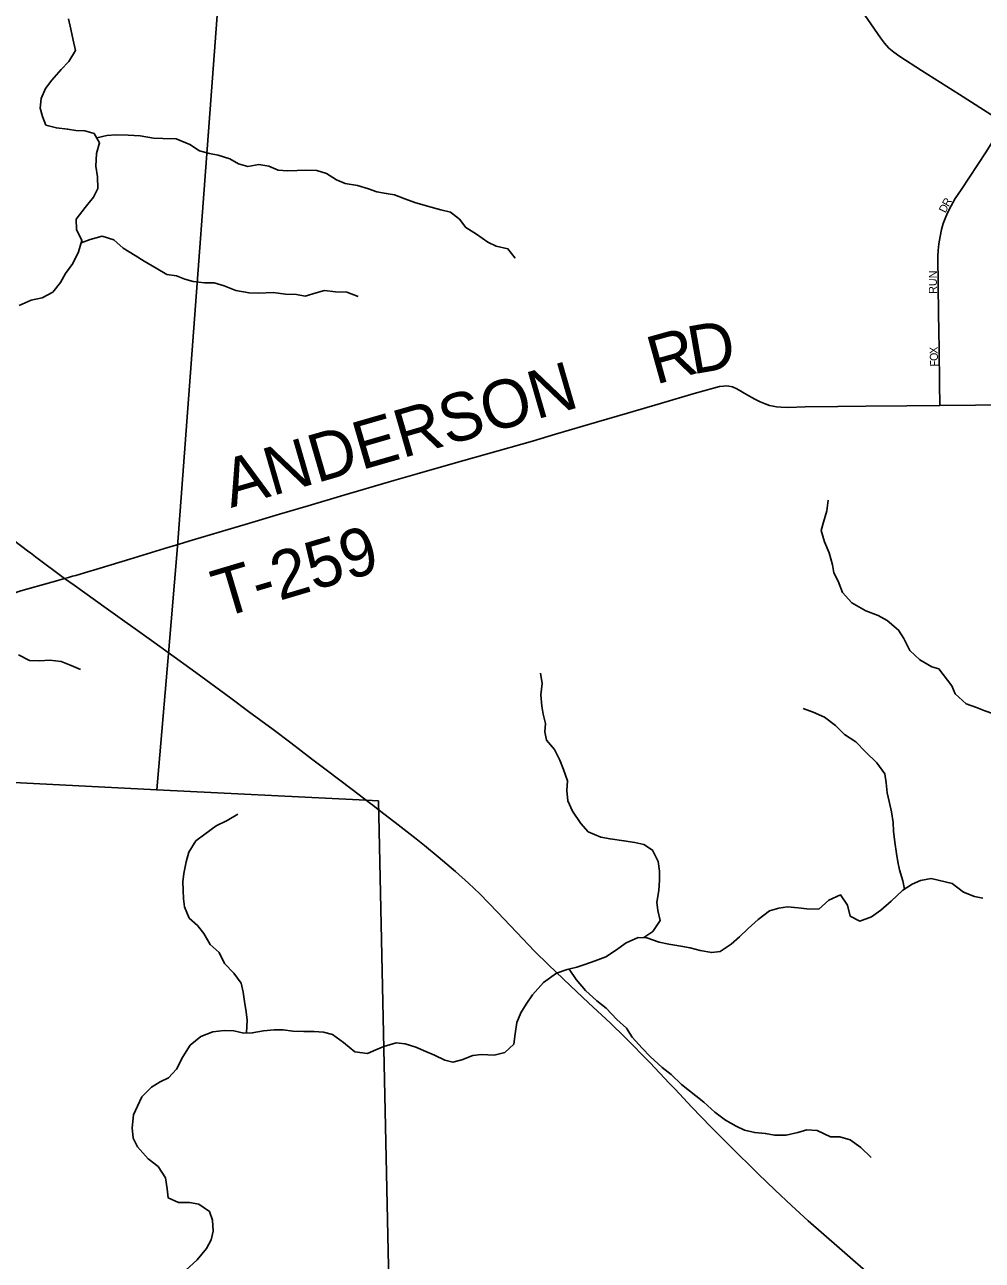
# Model space of a CAD drawing. Extents: x 1442749 to 1756758, y 235267 to 677782.
# Drawn here: x 1574676 to 1580655, y 536473 to 544190 of the extents above; entities that cross this region are included whole.
import ezdxf

# ---------------------------------------------------------------- set-up
doc = ezdxf.new("R2010")
doc.units = 0
for name, color, linetype in [('GM_X_County_Road', 7, 'Continuous'), ('GM_X_Major_River', 7, 'Continuous'), ('GM_X_Minor_River', 7, 'Continuous'), ('GM_X_State_Route', 7, 'Continuous'), ('GM_X_Township', 7, 'Continuous'), ('GM_X_Township_Road', 7, 'Continuous'), ('GM_X_Township_Road_Text', 7, 'Continuous'), ('GM_X_Township_Subdivision', 7, 'Continuous'), ('GM_X_Township_Subdivision_Text', 7, 'Continuous')]:
    doc.layers.add(name, color=color, linetype=linetype)

msp = doc.modelspace()

# ---------------------------------------------------------------- linework, layer by layer
at = {"layer": 'GM_X_County_Road'}
for points in [[(1579800.4, 544427.6), (1580018.8, 544108.2), (1580045, 544075), (1580072.2, 544044.6), (1580103.2, 544018.7), (1580139.8, 543991.7), (1580275, 543905.1), (1580513, 543753.6), (1580736.8, 543610.2)], [(1574565.9, 539401), (1574562.6, 539789.4), (1574561.3, 539916.8), (1574559.2, 540070.2), (1574557.6, 540184.8), (1574556.2, 540293), (1574553.5, 540476.5), (1574555.5, 540552.4), (1574557.3, 540565.8), (1574559.3, 540575.6), (1574561.7, 540586.3), (1574569, 540601.4), (1574576.8, 540612.2), (1574587.6, 540622.4), (1574597.8, 540630.3), (1574608.1, 540637.1), (1574617.4, 540642), (1574627.6, 540646.9), (1574651.5, 540654.2), (1574845.2, 540708.9), (1574867.7, 540715.4), (1574924.4, 540732.1)]]:
    msp.add_lwpolyline(points, dxfattribs=at)
at = {"layer": 'GM_X_Major_River'}
for points in [[(1576044.8, 537892.5), (1576096.8, 537893.1), (1576167.2, 537907.2), (1576233.4, 537913.4), (1576289.3, 537911.8), (1576349.1, 537904.1), (1576419.1, 537902.2), (1576483.1, 537902.4), (1576541, 537898.8), (1576598.5, 537883.2), (1576667.1, 537833.2), (1576737.4, 537775.2), (1576815.2, 537765.1), (1576867.8, 537787.6), (1576918.4, 537808.3), (1576995.1, 537832.2), (1577050.9, 537824.6), (1577118.3, 537804.7), (1577179.5, 537777), (1577234.8, 537753.4), (1577298, 537723.6), (1577349.6, 537710.2), (1577406, 537724.7), (1577474.8, 537752.8), (1577527, 537757.4), (1577606.9, 537753.2), (1577673.4, 537771.3), (1577728.9, 537823.9), (1577738.7, 537887.7), (1577748.7, 537957.5), (1577774.5, 538018.9), (1577806, 538072.1), (1577845.7, 538131.1), (1577915.9, 538207.3), (1577995.6, 538267.2), (1578062.2, 538289.3), (1578122.6, 538303.7), (1578173.1, 538320.3), (1578237.8, 538342.6), (1578304.5, 538368.8), (1578363.6, 538407.2), (1578431, 538455.4), (1578506, 538489.3), (1578559.9, 538487.9), (1578637.1, 538459.7), (1578696.8, 538448), (1578772.5, 538435.9), (1578830.1, 538424.3), (1578893.7, 538408.5), (1578965.3, 538394.5), (1579017.5, 538401.1), (1579086.8, 538447.2), (1579138.1, 538493.9), (1579193.6, 538544.4), (1579255.2, 538600.8), (1579326.8, 538654.9), (1579385.3, 538673.3), (1579437.5, 538679.9), (1579505.3, 538674), (1579559.2, 538668.5), (1579633.1, 538666.4), (1579696.7, 538722.8), (1579769.7, 538754.8), (1579813.8, 538691.5), (1579829.9, 538622.9), (1579891, 538591.2), (1579963.7, 538617.2), (1580020.9, 538659.7), (1580086.6, 538716), (1580158.5, 538784.1), (1580217.6, 538822.5), (1580268.3, 538845.1), (1580334.6, 538857.3)], [(1580334.6, 538857.3), (1580465.9, 538827.4), (1580536.8, 538771.8), (1580606.3, 538744.2), (1580658.3, 538735.1)], [(1575682.4, 536412.4), (1575752.2, 536476.5), (1575810.2, 536547), (1575839.7, 536600.3), (1575853.3, 536654), (1575849.3, 536724.2), (1575828.8, 536776.9), (1575762.1, 536822.8), (1575704.4, 536834.4), (1575636.4, 536834.3), (1575571.3, 536864.1), (1575564.8, 536918.4), (1575554.9, 536988.8), (1575508.8, 537058.1), (1575446.2, 537105.9), (1575380.4, 537181.9), (1575353.9, 537236.7), (1575345.8, 537301), (1575356.1, 537380.8), (1575379.7, 537436.3), (1575407.3, 537493.6), (1575467, 537554), (1575522, 537588.6), (1575572.7, 537613.2), (1575624.3, 537667.8), (1575662.5, 537742.9), (1575708.6, 537815.7), (1575776.1, 537869.9), (1575851, 537899.9), (1575921.2, 537908), (1575981.2, 537906.3), (1576044.8, 537892.5)]]:
    msp.add_lwpolyline(points, dxfattribs=at)
at = {"layer": 'GM_X_Minor_River'}
for points in [[(1575120.8, 543306.7), (1575124.4, 543384.8), (1575143.8, 543452.5), (1575109, 543511.3), (1575051.4, 543528.4), (1574995.4, 543529.5), (1574943.6, 543538.6), (1574873.7, 543546), (1574808.1, 543563.3), (1574787.2, 543617.8), (1574772.2, 543668.2), (1574779.5, 543730.1), (1574804.7, 543791.7), (1574845.8, 543843), (1574903.2, 543909.9), (1574952.2, 543961.1), (1574993.6, 544028.3), (1574979, 544094.7), (1574964.4, 544163.1), (1574949.7, 544227.5)], [(1575125.7, 543483), (1575188.8, 543497.7), (1575244.9, 543502.6), (1575320.9, 543501.1), (1575396.8, 543495.6), (1575480.5, 543481.9), (1575538.4, 543478.7), (1575622.4, 543477.1), (1575707.7, 543441.3), (1575766.9, 543402.1), (1575830.5, 543384.8), (1575884.4, 543375.8), (1575955.9, 543352.3), (1576011.3, 543321.2), (1576068.9, 543304), (1576137.2, 543316.7), (1576201, 543307.4), (1576258.5, 543282.2), (1576316.4, 543277.1), (1576376.5, 543279.9), (1576428.5, 543280.9), (1576500.5, 543279.4), (1576560.1, 543260.2), (1576623.3, 543220.9), (1576676.8, 543197.8), (1576754.6, 543186.3), (1576822.2, 543164.9), (1576873.8, 543145.9), (1576933.6, 543136.7), (1576985.4, 543127.6), (1577048.9, 543102.3), (1577112.5, 543079), (1577190, 543057.5), (1577273.6, 543033.8), (1577335.3, 543018.6), (1577390.4, 542975.4), (1577429.3, 542924.6), (1577496.5, 542881.2), (1577567.5, 542831.7), (1577618.9, 542806.6), (1577692.6, 542791.2), (1577737.4, 542732.2)], [(1574640.9, 542436.9), (1574715.6, 542469.5), (1574783.9, 542484.1), (1574850.6, 542518.9), (1574899.9, 542580), (1574931, 542635.5), (1574976.3, 542698.7), (1575011.9, 542772.1), (1575033.3, 542841.8), (1574998.7, 542910.5), (1574998, 542976.7), (1575053.5, 543047.7), (1575104.9, 543112.8), (1575132, 543166.3), (1575129.5, 543240.5), (1575120.8, 543306.7)], [(1575029.3, 542828.9), (1575085.4, 542848.7), (1575159.9, 542869.3), (1575231.4, 542845.8), (1575290.4, 542794.6), (1575365.4, 542749), (1575420.7, 542713.9), (1575495.8, 542670.4), (1575563, 542631), (1575622.9, 542621.8), (1575676.4, 542600.7), (1575728.1, 542585.6), (1575798, 542578.2), (1575858, 542577.1), (1575921.6, 542559.8), (1575995, 542530.3), (1576076.7, 542514.7), (1576138.7, 542513.4), (1576226.8, 542517.7), (1576304.6, 542508.1), (1576372.6, 542504.8), (1576426.4, 542495.7), (1576494.8, 542516.4), (1576547.1, 542529.4), (1576617, 542522), (1576686.9, 542520.6), (1576758.4, 542493.2)], [(1580384.1, 540168), (1580339.5, 540178.9), (1580264.4, 540224.4), (1580201.5, 540281.8), (1580165.1, 540356.6), (1580132.1, 540409.3), (1580061.4, 540468.8), (1580004, 540500), (1579926.6, 540529.6), (1579839.6, 540579.4), (1579780.9, 540644.6), (1579754.4, 540715.3), (1579727.4, 540765.9), (1579720.4, 540816.1), (1579698, 540892.7), (1579669.4, 540961.3), (1579648.8, 541031.8), (1579663.9, 541083.6), (1579683.3, 541153.3), (1579692.7, 541221.3)], [(1574636.1, 540253.7), (1574705.5, 540220.2), (1574767.4, 540217), (1574833.5, 540221.7), (1574903.3, 540212.3), (1574966.9, 540189), (1575024.4, 540163.8)], [(1578540.5, 538488.4), (1578597.3, 538526.8), (1578642.7, 538596), (1578628, 538658.4), (1578623.1, 538710.5), (1578634.5, 538782.4), (1578639.9, 538846.4), (1578639, 538902.5), (1578630.3, 538964.8), (1578595.7, 539035.6), (1578542.5, 539070.7), (1578484.7, 539081.8), (1578416.9, 539093.2), (1578331.1, 539104.9), (1578273.3, 539116.1), (1578194, 539149.7), (1578147.1, 539200.7), (1578096.6, 539277.8), (1578068, 539342.5), (1578061.3, 539406.7), (1578064.5, 539466.7), (1578040, 539539.3), (1578017.1, 539595.9), (1577984.5, 539662.6), (1577933.7, 539721.7), (1577922.8, 539774), (1577927.9, 539826), (1577913, 539884.4), (1577904.1, 539934.6), (1577897.5, 540004.8), (1577907, 540074.8), (1577896.3, 540139.1)], [(1580973, 539840.7), (1580899.1, 539843.8), (1580849.1, 539848.4), (1580783.1, 539865.2), (1580725.2, 539885.9), (1580671.4, 539904.6), (1580619.5, 539925.2), (1580553.6, 539948), (1580486.2, 540011), (1580464.8, 540061.4), (1580384.1, 540168)], [(1580169.4, 538791.2), (1580158, 538842.4), (1580137.4, 538910.9), (1580126.4, 538961.2), (1580119.5, 539013.4), (1580109, 539083.8), (1580100.4, 539154), (1580097.5, 539208.2), (1580086.9, 539274.5), (1580074.2, 539338.8), (1580061.3, 539393.2), (1580054.6, 539455.4), (1580045.7, 539511.7), (1579997.1, 539580.8), (1579926.5, 539648.2), (1579865.8, 539711.5), (1579794.7, 539757), (1579737.9, 539814.2), (1579668.9, 539865.7), (1579599.6, 539897.1), (1579536, 539920.4)], [(1576060, 537892.7), (1576065.5, 537971.9), (1576058.6, 538024.1), (1576048, 538090.4), (1576039.1, 538146.7), (1576028.3, 538203), (1575981.6, 538266), (1575922.8, 538327.3), (1575890.2, 538396), (1575833.2, 538445.2), (1575794.6, 538514.1), (1575753.7, 538565), (1575702.6, 538610.1), (1575674, 538680.7), (1575667, 538731), (1575664.2, 538785.1), (1575663.2, 538837.2), (1575670.3, 538889.1), (1575683.8, 538961), (1575701, 539022.7), (1575744.5, 539092), (1575801.4, 539134.9), (1575870.5, 539187.6), (1575939.1, 539220.3), (1576005.9, 539259.1)], [(1578075, 538292.3), (1578119.1, 538227.8), (1578177.7, 538158.5), (1578248.4, 538093), (1578305.4, 538047.8), (1578372, 537976.4), (1578432.9, 537923.1), (1578467.7, 537866.3), (1578530.3, 537797), (1578581.3, 537745.9), (1578655.9, 537676.3), (1578713, 537633.1), (1578777.7, 537571.7), (1578915.5, 537460.8), (1578984.2, 537397.4), (1579051.2, 537348), (1579118.4, 537310.6), (1579169.9, 537285.5), (1579233.6, 537270.3), (1579299.5, 537265), (1579359.3, 537253.8), (1579429.3, 537254.4), (1579503.7, 537270.9), (1579560, 537287.8), (1579624, 537284.6), (1579707.2, 537244.9), (1579765.2, 537243.7), (1579830.8, 537224.4), (1579895.8, 537177), (1579960.6, 537115.7)]]:
    msp.add_lwpolyline(points, dxfattribs=at)
at = {"layer": 'GM_X_State_Route'}
for points in [[(1574553.3, 541010.5), (1574702.4, 540898.8), (1574712.6, 540890.8), (1574744, 540867.5), (1574924.4, 540732.1), (1574985.5, 540689.6), (1575183.9, 540546.1), (1575467.4, 540344.8), (1575571.8, 540269.3), (1575743.7, 540144.6), (1575963.3, 539983.3), (1576073.9, 539901.3), (1576226.8, 539788.2), (1576336.7, 539704.9), (1576467, 539605.4), (1576558.6, 539536.2), (1576720.6, 539413.1), (1576834.1, 539326.7), (1576849.1, 539315.3), (1576872, 539297.9), (1576972.7, 539220.7), (1576988.9, 539207.7), (1577120.4, 539104.4), (1577171.2, 539063.5)], [(1577171.2, 539063.5), (1577258.3, 538993.3), (1577366, 538902.1), (1577446.2, 538829.1), (1577516.8, 538761.4), (1577627.3, 538648.4), (1577748.6, 538519.5), (1577859.8, 538403.7), (1577945.5, 538318.2), (1578083.2, 538187), (1578195.7, 538081.7), (1578333, 537954.6), (1578424.3, 537864.8), (1578580.6, 537705.6), (1578699.2, 537580.3)], [(1578699.2, 537580.3), (1578736.2, 537541.2), (1578841.8, 537429.3), (1578959.9, 537306.7), (1579077.5, 537188.1), (1579255.3, 537013.4), (1579361.5, 536911.1), (1579463.9, 536814.3), (1579568.2, 536719.7), (1579763, 536549), (1579978.2, 536361.4), (1580033.5, 536313.3), (1580045.3, 536303)]]:
    msp.add_lwpolyline(points, dxfattribs=at)
at = {"layer": 'GM_X_Township'}
for points in [[(1567480, 573617.6), (1572928.5, 573040.3), (1578512.8, 572448.5), (1578437.8, 571716.9), (1577744.9, 564960.2), (1577349.2, 561102), (1576813.8, 555881.3), (1576704.1, 554811.5), (1576385.5, 550843.6), (1576369, 550638.4), (1576189.1, 548397.4), (1576128.9, 547648.1), (1575922.4, 544864.2), (1575630.5, 540930.9), (1575571.3, 540238.8), (1575500.4, 539411), (1574567.9, 539458.5), (1566007.1, 539894.4)], [(1577335.5, 518378.1), (1577246.7, 522507.3), (1577095.4, 529536.7), (1576886.4, 539252.1), (1576884.4, 539342.6), (1576764.1, 539348.5), (1575500.4, 539411), (1575571.3, 540238.8), (1575630.5, 540930.9), (1575922.4, 544864.2), (1576128.9, 547648.1), (1576189.1, 548397.4), (1576369, 550638.4), (1576385.5, 550843.6), (1576704.1, 554811.5), (1579969, 554625.3), (1580170.1, 554613.8), (1584797.1, 554350), (1586587.6, 554237.2), (1589106.2, 554078.6), (1593926.1, 553600.7)], [(1566007.1, 539894.4), (1574567.9, 539458.5), (1575500.4, 539411), (1576764.1, 539348.5), (1576884.4, 539342.6), (1576886.4, 539252.1), (1577095.4, 529536.7), (1577246.7, 522507.3), (1577335.5, 518378.1), (1577466, 512312.2), (1577284.9, 512328.8), (1572224.6, 512792.5), (1572116.5, 513572.1), (1570495.5, 513586.9), (1570073.6, 513943.9), (1565959.1, 517425.5)]]:
    msp.add_lwpolyline(points, dxfattribs=at)
at = {"layer": 'GM_X_Township_Road'}
for points in [[(1575619, 540940), (1575722.1, 540971.4), (1575945.4, 541037.9), (1576052.5, 541069), (1576266.4, 541132.6), (1576445.7, 541185.8), (1576669, 541252.2), (1576788.7, 541287.2), (1576980.5, 541344.2), (1577125.7, 541385.3), (1577337, 541446.2), (1577564.8, 541509), (1577845.4, 541590), (1577990.2, 541632.1), (1578245.1, 541707.4), (1578440.4, 541764.3), (1578645.1, 541824.1), (1578856.1, 541885.9), (1578976.1, 541920.3), (1579014.7, 541929.9), (1579038, 541933.5), (1579054.8, 541934.6), (1579071.7, 541933.4), (1579094.8, 541927.8), (1579122.4, 541915.4), (1579182.5, 541880.9), (1579233.6, 541851.5), (1579268.4, 541834), (1579298.4, 541821.4), (1579326, 541812.4), (1579348, 541807.2), (1579370.3, 541803.6), (1579399.3, 541801.1), (1579441.7, 541800.4), (1579549.8, 541802.8), (1579753.3, 541806.1), (1579927.2, 541808.2), (1580183.2, 541810.5), (1580390.5, 541812.3)], [(1580390.5, 541812.3), (1580836, 541816.7)], [(1574924.4, 540732.1), (1574949.7, 540738.3), (1574974, 540745), (1574995, 540750.7), (1575048.5, 540767.4), (1575147.6, 540796.8), (1575333, 540852.7), (1575549.5, 540918.8), (1575619, 540940)]]:
    msp.add_lwpolyline(points, dxfattribs=at)
at = {"layer": 'GM_X_Township_Subdivision'}
msp.add_lwpolyline([(1580390.5, 541812.3), (1580388.2, 541950.7), (1580385.3, 542163.7), (1580384.3, 542275.3), (1580382.2, 542386.7), (1580380.1, 542563.8), (1580377.5, 542744), (1580379.5, 542780.1), (1580383.7, 542821.8), (1580390.8, 542866.8), (1580400.8, 542911.3), (1580411.4, 542948.9), (1580422.5, 542979.4), (1580438.3, 543015.1), (1580460.4, 543058.7), (1580486.3, 543104.1), (1580521.8, 543159), (1580678.6, 543397.1), (1580779.7, 543556.4), (1580791.7, 543575.1)], dxfattribs=at)

# ---------------------------------------------------------------- texts
at = {"layer": 'GM_X_Township_Road_Text'}
for s, rotation, p in [('R', 15.6012, (1578614.9, 541941.1)), ('D', 9.93634, (1578844.6, 542005.6)), ('ANDERSON', 16.15069, (1575963.5, 541171.7)), ('T-259', 16.59315, (1575902.8, 540483.2))]:
    msp.add_text(s, height=300, rotation=rotation, dxfattribs=at).set_placement(p)
at = {"layer": 'GM_X_Township_Subdivision_Text'}
for s, rotation, p in [('D', 63.08314, (1580424.7, 543010.9)), ('R', 61.11048, (1580444.4, 543049.7)), ('RUN', 90, (1580371, 542509.5)), ('X', 91.53045, (1580376.6, 542134.9)), ('O', 92.30434, (1580378.4, 542091.1)), ('F', 92.29498, (1580379.8, 542055.9))]:
    msp.add_text(s, height=50, rotation=rotation, dxfattribs=at).set_placement(p)

doc.saveas('drawing.dxf')
